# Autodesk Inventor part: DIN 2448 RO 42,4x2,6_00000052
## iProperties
Created: 2006-03
Part Number: DIN 2448 RO 42,4x2,6_00000052
Material: Default
Document SubType Name: Modeling
Designer: Carlo
Stock Number: DIN 2448 RO 42,4x2,6
Mass: 577.032 g
Surface Area: 4452.08 cm^2
Volume: 577.032 cm^3
Density: 1 g/cm^3
G_L: 1805.000 mm
G_W: 42.400 mm
G_H: 42.400 mm
AFG_Item: 42.4 x 2.6
CSToolsMass: 1.0
CSToolsVolume: 577032.0
CSToolsArea: 4452.0
Author: Carlo
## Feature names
1. AFG_Detailed_DIN 2448 RO 42,4x2,6_00000052 [Extrusion]
2. AFG_Simplified_DIN 2448 RO 42,4x2,6_00000052 [Extrusion]
3. AFG_StartExtrusion_1 [Extrusion]
4. AFG_StartExtrusion_2 [Extrusion]
5. AFG_EndExtrusion_1 [Extrusion]
6. AFG_EndExtrusion_2 [Extrusion]
